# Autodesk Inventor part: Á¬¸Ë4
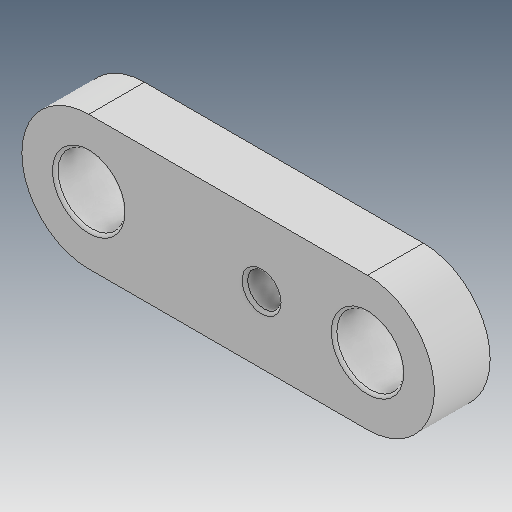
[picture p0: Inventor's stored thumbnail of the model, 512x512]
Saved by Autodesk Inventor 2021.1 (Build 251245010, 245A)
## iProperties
Created: 2013-04
Part Number: Á¬¸Ë4
Material: Ogólny
Document SubType Name: Modeling
Designer: user
Density: 1 g/cm^3
Appearance: Domyślna
Author: user
Revision Number: ÈÎºÎ
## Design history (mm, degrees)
feature "Ô²½Ç1"
node "Bryła1"
